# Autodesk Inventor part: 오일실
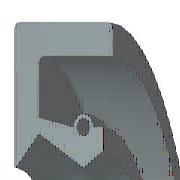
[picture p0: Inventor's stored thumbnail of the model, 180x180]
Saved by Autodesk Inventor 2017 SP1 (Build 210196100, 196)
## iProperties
Created: 2021-07
Part Number: 오일실
Material: 고무
Description: 오일-실
Document SubType Name: Modeling
Standard: KS B 2804
Designer: mdu
Standards Organization: KS
Language: ko-KR
Size Designation: D - 10 20 7
Categories: <MemberInstance><Categories><Category DisplayName="샤프트 부품" InternalName="7f7aeb1f-a693-4053-b835-cee3144e0d98" Mnemonic="SHFT"><Category DisplayName="실링" Intern
Density: 0.93 g/cm^3
Mass: 1.11329 g
Surface Area: 16.3871 cm^2
Volume: 1.19708 cm^3
Appearance: 고무 - 검은색 - 버전 1.1
IsCustomPart: 0
Author: mdu
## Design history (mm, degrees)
revolve "본체" stored, may be unused: angle "d17" = 90 deg
revolve "스프링1" stored, may be unused: angle "d18" = 90 deg
body "Solid1"
sketch "스케치1"
  geometry: L1 (0, 10)-(7, 10); L2 (7, 8.25)-(1.75, 8.25); L3 (1.75, 6.75)-(4.9, 5); L4 (4.9, 5)-(0, 5); L5 (0, 0)-(9.586, 0) reference; L6 (4.9, 5)-(6.3, 5.875); L7 (0, 18)-(0, -3) reference; L8 (-1.941, 0)-(11.507, 0) reference; L9 (4.2, 7.1)-(1.75, 7.59); L10 (1.75, 7.59)-(1.75, 8.25); L11 (0, 10)-(0, 5.088); L12 (4.9, 5)-(0, 5); L13 (1.75, 6.75)-(0.152, 5.028); L14 (7, 10)-(7, 8.25); L15 (5.6, 7.1)-(6.3, 7.1); L16 (6.3, 7.1)-(6.3, 5.875); C1 r 0.455 at (4.9, 7.1); A1 r 0.7 centre (4.9, 7.1) between (5.6, 7.1) and (4.2, 7.1); A2 r 0.088 centre (0.088, 5.088) between (0, 5.088) and (0.152, 5.028); 1 further point
  constraints: 28 end point, 5 horizontal alignment, 5 point on line, 4 point on circle, 4 vertical alignment, 3 centre point, 3 tangent, 2 collinear, 2 horizontal, 2 perpendicular, 1 coincident, 1 parallel
  dimensions: "d0" = 20 diameter of L1 L5 (= SD2); "d1" = 1.75 distance of L1.end L2.start (= SD); "d2" = 0.91 diameter of C1 (= SPDI); "d3" = 1.4 diameter of A1 (= SPDA); "d4" = 10 diameter of L3.end L5 (= NND); "d5" = 13.5 diameter of L3.start L5 (= TKDM); "d7" = 15.18 diameter of L9.end L5 (= TKDM + 0.24 x SWDT); "d8" = 1.75 distance between parallel lines of L11 L10 (= SD); "d9" = 4.9 distance from line of L11 C1.centre (= SPDST); "d10" = 14.2 diameter of C1.centre L5 (= HLDM); "d11" = 0.0875 radius of A2 (= 0.25 x LAB); "d12" = 6.3 distance between parallel lines of L11 L16 (= SDI); "d13" = 11.75 diameter of L6.end L5 (= ABDM); "d14" = 7 distance from line of L11 L1.end (= SWDT)
fillet "모깎기1" dims "d6" = 0.3 (= RR)
other parameters: "SD2" = 20 [user parameter; used in 1 equation term], "SWDT" = 7 [user parameter; used in 2 equation terms], "RR" = 0.3 [user parameter; used in 1 equation term], "SD" = 1.75 [user parameter; used in 2 equation terms], "NND" = 10 [user parameter; used in 1 equation term], "SPDA" = 1.4 [user parameter; used in 1 equation term], "SPDI" = 0.91 [user parameter; used in 1 equation term], "TKDM" = 13.5 [user parameter; used in 2 equation terms], "HLDM" = 14.2 [user parameter; used in 1 equation term], "ABDM" = 11.75 [user parameter; used in 1 equation term], "SDI" = 6.3 [user parameter; used in 1 equation term], "SPDST" = 4.9 [user parameter; used in 1 equation term], "LAB" = 0.35 [user parameter; used in 1 equation term], "d15" = 0, "d16" = 0, "d19" = 0
